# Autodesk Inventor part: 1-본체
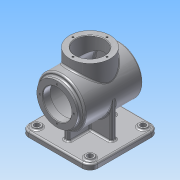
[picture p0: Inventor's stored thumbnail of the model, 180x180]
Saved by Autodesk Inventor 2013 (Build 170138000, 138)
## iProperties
Created: 2015-07
Part Number: 1-본체
Material: 알루미늄 6061
Document SubType Name: Modeling
Designer: Administrator
Density: 2.71 g/cm^3
Mass: 1279.26 g
Surface Area: 1271.88 cm^2
Volume: 472.05 cm^3
Author: Administrator
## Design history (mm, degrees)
sketch "스케치1"
  geometry: C1 r 45 at (0, 0); 1 further point
  constraints: 1 centre point, 1 coincident
  dimensions: "d0" = 90 diameter of C1
extrude "돌출1" new body sketch "스케치1" stored distance "d2" = 110; taper "d3" = 0 deg
node "작업 평면1"
sketch "스케치2"
  geometry: L1 (-50, 65)-(50, 65); L2 (65, 50)-(65, -50); L3 (50, -65)-(-50, -65); L4 (-65, -50)-(-65, 50); A1 r 15 centre (-50, 50) between (-50, 65) and (-65, 50); A2 r 15 centre (-50, -50) between (-65, -50) and (-50, -65); A3 r 15 centre (50, -50) between (50, -65) and (65, -50); A4 r 15 centre (50, 50) between (65, 50) and (50, 65); 6 further points
  constraints: 8 end point, 8 point on circle, 8 point on line, 8 tangent, 4 centre point, 3 equal radius, 2 parallel, 1 horizontal, 1 midpoint, 1 perpendicular, 1 vertical alignment
  dimensions: "d5" = 130 distance between parallel lines of L2 L4; "d7" = 65 distance from line of L3 point (0, 0); "d8" = 130 distance between parallel lines of L3 L1; "d11" = 15 radius of A1
extrude "돌출2" join sketch "스케치2" distance "d9" = 10; taper "d10" = 0 deg
sketch "스케치3"
  geometry: L1 (-50, -68)-(-65, -68) reference; L2 (50, -68)-(-50, -68) reference; L3 (65, -68)-(50, -68) reference; L4 (-45, -68)-(-45, 0); L5 (-45, 0)-(45, 0); L6 (45, 0)-(45, -68); C1 r 45 at (0, 0) reference; 2 further points
  constraints: 6 end point, 3 perpendicular, 2 point on line, 1 coincident, 1 midpoint, 1 tangent
  dimensions: "d14" = 68 distance between parallel lines of L2 L5
extrude "돌출3" join sketch "스케치3" stored distance "d16" = 10; taper "d17" = 0 deg
sketch "스케치4"
  geometry: L1 (-68, 50)-(-68, 65) reference; L2 (-68, -50)-(-68, 50) reference; L3 (-68, -65)-(-68, -50) reference; L4 (45, 55)-(-45, 55) reference; L5 (-45, -55)-(45, -55) reference; L6 (-68, 45)-(2, 45); L7 (2, 45)-(2, -45); L8 (2, -45)-(-68, -45); 2 further points
  constraints: 6 end point, 2 perpendicular, 2 point on line, 1 horizontal alignment, 1 midpoint, 1 parallel
  dimensions: "d18" = 90 distance between parallel lines of L8 L6; "d20" = 70 distance between parallel lines of L2 L7
extrude "돌출4" join sketch "스케치4" stored distance "d21" = 10; taper "d22" = 0 deg
sketch "스케치5"
  geometry: C1 r 38 at (0, 0); 1 further point
  constraints: 1 centre point, 1 coincident
  dimensions: "d23" = 76 diameter of C1
extrude "돌출5" join sketch "스케치5" distance "d25" = 62; taper "d26" = 0 deg
sketch "스케치6"
  geometry: C1 r 38 at (0, 0); 1 further point
  constraints: 1 centre point, 1 coincident
  dimensions: "d27" = 76 diameter of C1
extrude "돌출6" join sketch "스케치6" distance "d29" = 62; taper "d30" = 0 deg
sketch "스케치7"
  geometry: L1 (0, 48)-(0, -48); L2 (0, 48)-(40, 48); L3 (40, 48)-(40, -48); L4 (40, -48)-(0, -48); 2 further points
  constraints: 8 end point, 2 perpendicular, 1 coincident, 1 midpoint, 1 parallel, 1 vertical
  dimensions: "d67" = 96 distance of L1.start L1.end; "d69" = 80 diameter of L3 L1
revolve "회전1" sketch "스케치7" stored, may be unused: angle "d70" = 90 deg
hole "구멍5" diameter "d73" = 54; stored, may be unused: countersink angle "d77" = 90 deg, drill point angle "d79" = 118 deg; dims "d71" = 10, "d72" = 10, "d74" = 6, "d75" = 4, "d76" = 2, "d78" = 14
hole "구멍6" diameter "d82" = 54; stored, may be unused: countersink angle "d86" = 90 deg, drill point angle "d88" = 118 deg; dims "d83" = 6, "d84" = 4, "d85" = 2, "d87" = 35, "d173" = 10, "d174" = 10
sketch "스케치8"
  geometry: 2 further points
  constraints: 1 vertical alignment
  dimensions: "d89" = 32 distance of point (0, 0) point (0, 32)
hole "구멍7" sketch "스케치8" at (0, 32) diameter "d90" = 3.242; stored, may be unused: countersink angle "d94" = 90 deg, drill point angle "d96" = 118 deg; dims "d91" = 8, "d92" = 4, "d93" = 2, "d95" = 10
sketch "스케치9"
  geometry: 2 further points
  constraints: 1 vertical alignment
  dimensions: "d100" = 32 distance of point (0, 0) point (0, 32)
hole "구멍8" sketch "스케치9" at (0, 32) diameter "d101" = 3.242; stored, may be unused: countersink angle "d105" = 90 deg, drill point angle "d107" = 118 deg; dims "d102" = 8, "d103" = 4, "d104" = 2, "d106" = 10
sketch "스케치10"
  geometry: C1 r 7.5 at (-50, 50); C2 r 7.5 at (50, 50); C3 r 7.5 at (50, -50); C4 r 7.5 at (-50, -50); 1 further point
  constraints: 4 centre point, 3 equal radius, 2 horizontal alignment, 2 vertical alignment
  dimensions: "d111" = 100 distance of C2.centre C1.centre; "d113" = 50 horizontal distance of C2.centre point (0, 0); "d114" = 100 distance of C3.centre C2.centre; "d115" = 50 horizontal distance of C3.centre point (0, 0); "d116" = 15 diameter of C2
extrude "돌출7" join sketch "스케치10" distance "d117" = 3; taper "d118" = 0 deg
hole "구멍9" diameter "d121" = 10; stored, may be unused: countersink angle "d125" = 90 deg, drill point angle "d127" = 118 deg; dims "d119" = 10, "d120" = 10, "d122" = 10, "d123" = 4, "d124" = 2, "d126" = 10
hole "구멍10" diameter "d130" = 10; stored, may be unused: countersink angle "d134" = 90 deg, drill point angle "d136" = 118 deg; dims "d128" = 10, "d129" = 10, "d131" = 10, "d132" = 4, "d133" = 2, "d135" = 10
hole "구멍11" diameter "d139" = 10; stored, may be unused: countersink angle "d143" = 90 deg, drill point angle "d145" = 118 deg; dims "d137" = 10, "d138" = 10, "d140" = 10, "d141" = 4, "d142" = 2, "d144" = 10
hole "구멍12" diameter "d148" = 10; stored, may be unused: countersink angle "d152" = 90 deg, drill point angle "d154" = 118 deg; dims "d146" = 10, "d147" = 10, "d149" = 10, "d150" = 4, "d151" = 2, "d153" = 10
sketch "스케치11"
  geometry: L1 (-23.291, 3.588)-(23.291, 3.588); L2 (23.291, 3.588)-(23.291, -3.588); L3 (23.291, -3.588)-(-23.291, -3.588); L4 (-23.291, -3.588)-(-23.291, 3.588); 4 further points
  constraints: 2 midpoint, 1 coincident, 1 horizontal alignment, 1 vertical, 1 vertical alignment, 2 other
  dimensions: "d155" = 46.58163 distance between parallel lines of L2 L4; "d156" = 7.17576 distance between parallel lines of L3 L1
feature "엠보싱1" sketch "스케치11" dims "d0" = 90, "d157" = 0.5, "d158" = 0
chamfer "모따기1" distance "d159" = 1; stored, may be unused: second distance "d160" = 2, angle "d161" = 45 deg
fillet "모깎기1" dims "d162" = 3
fillet "모깎기2" dims "d163" = 3
fillet "모깎기3" dims "d164" = 3
fillet "모깎기4" dims "d165" = 3
fillet "모깎기5" dims "d166" = 3
fillet "모깎기6" dims "d167" = 3
fillet "모깎기7" dims "d168" = 3
fillet "모깎기8" dims "d169" = 3
fillet "모깎기9" dims "d170" = 3
fillet "모깎기10" dims "d171" = 3
fillet "모깎기11" dims "d172" = 3
node "솔리드1"
pattern_circular "원형 패턴1" dims angle "d98" = 360 deg
pattern_circular "원형 패턴2" dims angle "d109" = 360 deg
other parameters: "d4" = -78
